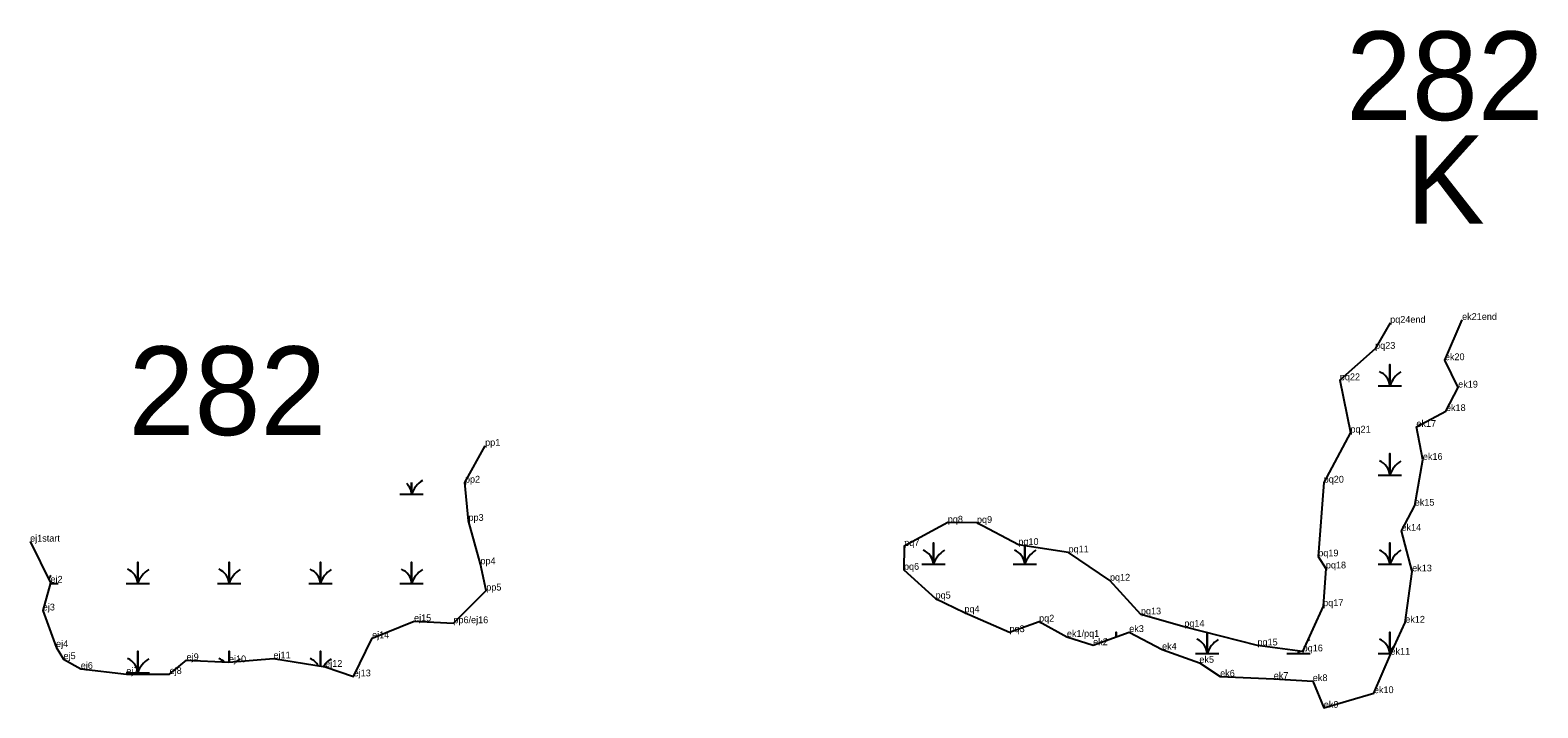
# Model space of a CAD drawing. Extents: x 2072529 to 2268796, y 436423 to 470406.
# Drawn here: x 2242590 to 2243701, y 441089 to 441588 of the extents above; entities that cross this region are included whole.
import ezdxf

# ---------------------------------------------------------------- set-up
doc = ezdxf.new("R2010")
doc.units = 0
for name, color, linetype in [('Default', 7, 'Continuous'), ('Exist Environmental Wetland Boundary', 7, 'Continuous'), ('Exist Environmental Wetland Boundary Cogo Comment', 7, 'Continuous'), ('Exist Hydro Swamp or Marsh', 7, 'Continuous'), ('Old_Level_20', 7, 'Continuous')]:
    doc.layers.add(name, color=color, linetype=linetype)

msp = doc.modelspace()

# ---------------------------------------------------------------- linework, layer by layer
at = {"layer": 'Exist Environmental Wetland Boundary'}
for points in [[(2243592.5, 441372.6), (2243581.4, 441353.4), (2243555.4, 441330.2), (2243563.2, 441291.6), (2243543.5, 441254.7), (2243539.5, 441200.3), (2243545.1, 441191.4), (2243543.1, 441163.6), (2243528, 441130.2), (2243494.7, 441134.6), (2243440.8, 441148.4), (2243408.8, 441157.5), (2243386, 441182.4), (2243355.5, 441203.2), (2243318.5, 441208.7), (2243288, 441225), (2243266.5, 441225.2), (2243234.4, 441207.9), (2243234.2, 441190.4), (2243257.5, 441169.2), (2243278.8, 441159), (2243312, 441144.4), (2243333.8, 441152.2), (2243354.3, 441140.9)], [(2243354.3, 441140.9), (2243373.6, 441134.8), (2243400.2, 441144.5), (2243424.4, 441131.5), (2243451.9, 441121.8), (2243467.2, 441111.6), (2243506.7, 441109.9), (2243535.5, 441108.3), (2243543.6, 441088.6), (2243580.5, 441099.4), (2243592.7, 441127.8), (2243603.6, 441151.4), (2243608.7, 441189.2), (2243600.8, 441219.2), (2243610.6, 441237.7), (2243616.6, 441271.5), (2243611.8, 441295.8), (2243633.6, 441307.5), (2243642.6, 441324.8), (2243632.8, 441345), (2243645.5, 441374.7)], [(2242590.3, 441211.2), (2242605.3, 441180.9), (2242599.6, 441160.4), (2242609.4, 441133.4), (2242614.9, 441124.5), (2242627.6, 441117.4), (2242661.2, 441113.4), (2242693.1, 441113.5), (2242705.6, 441123.7), (2242736.8, 441122.2), (2242769.6, 441125), (2242807.7, 441118.8), (2242828.7, 441111.8), (2242842.3, 441139.9), (2242873.2, 441152.5), (2242902.2, 441151), (2242926.4, 441175.1), (2242922.1, 441194.5), (2242913.3, 441226.5), (2242910.7, 441254.7), (2242925.6, 441281.9)]]:
    msp.add_lwpolyline(points, dxfattribs=at)
at = {"layer": 'Exist Hydro Swamp or Marsh'}
for points in [[(2243583.6, 441326.1), (2243592.2, 441326.1), (2243592.2, 441341.9), (2243592.2, 441326.1), (2243600.8, 441326.1)], [(2243583.6, 441260.3), (2243592.2, 441260.3), (2243592.2, 441276.1), (2243592.2, 441260.3), (2243600.8, 441260.3)], [(2242862.8, 441246.1), (2242871.4, 441246.1), (2242871.4, 441254.9)], [(2242871.4, 441254.9), (2242871.4, 441246.1), (2242880, 441246.1)], [(2243247.4, 441194.5), (2243256, 441194.5), (2243256, 441210.3), (2243256, 441194.5), (2243264.6, 441194.5)], [(2243583.6, 441194.5), (2243592.2, 441194.5), (2243592.2, 441210.3), (2243592.2, 441194.5), (2243600.8, 441194.5)], [(2243314.6, 441194.5), (2243323.2, 441194.5), (2243323.2, 441208)], [(2243323.2, 441208), (2243323.2, 441194.5), (2243331.8, 441194.5)], [(2242661.1, 441180.3), (2242669.7, 441180.3), (2242669.7, 441196.1), (2242669.7, 441180.3), (2242678.3, 441180.3)], [(2242728.3, 441180.3), (2242736.9, 441180.3), (2242736.9, 441196.1), (2242736.9, 441180.3), (2242745.5, 441180.3)], [(2242795.6, 441180.3), (2242804.2, 441180.3), (2242804.2, 441196.1), (2242804.2, 441180.3), (2242812.8, 441180.3)], [(2242862.8, 441180.3), (2242871.4, 441180.3), (2242871.4, 441196.1), (2242871.4, 441180.3), (2242880, 441180.3)], [(2242605.1, 441180.3), (2242611, 441180.3)], [(2243390.5, 441140.9), (2243390.5, 441144.5), (2243390.5, 441140.9)], [(2243449.1, 441128.7), (2243457.7, 441128.7), (2243457.7, 441144.1)], [(2243457.7, 441144.1), (2243457.7, 441128.7), (2243466.3, 441128.7)], [(2243583.6, 441128.7), (2243592.2, 441128.7), (2243592.2, 441144.5), (2243592.2, 441128.7), (2243593.1, 441128.7)], [(2242661.1, 441114.5), (2242669.7, 441114.5), (2242669.7, 441130.3), (2242669.7, 441114.5), (2242678.3, 441114.5)], [(2242736.9, 441122.2), (2242736.9, 441130.3), (2242736.9, 441122.2)], [(2242804.2, 441119.3), (2242804.2, 441130.3), (2242804.2, 441119.3)], [(2243516.4, 441128.7), (2243525, 441128.7), (2243525, 441130.6)], [(2243525, 441130.6), (2243525, 441128.7), (2243533.6, 441128.7)]]:
    msp.add_lwpolyline(points, dxfattribs=at)
for centre, radius, start, end in [((2243579.9, 441325.2), 12.3, 4.1403, 67.535), ((2243610.5, 441320.1), 19.2, 122.1274, 161.6222), ((2243579.9, 441259.4), 12.3, 4.1403, 67.535), ((2243610.5, 441254.3), 19.2, 122.1274, 161.6222), ((2242859.2, 441245.2), 12.3, 4.1403, 45.821), ((2242889.7, 441240.1), 19.2, 122.1274, 161.6222), ((2243243.7, 441193.6), 12.3, 4.1403, 67.535), ((2243274.2, 441188.5), 19.2, 122.1274, 161.6222), ((2243310.9, 441193.6), 12.3, 4.1403, 67.535), ((2243341.5, 441188.5), 19.2, 122.1274, 161.6222), ((2243579.9, 441193.6), 12.3, 4.1403, 67.535), ((2243610.5, 441188.5), 19.2, 122.1274, 161.6222), ((2242657.4, 441179.4), 12.3, 4.1403, 67.535), ((2242687.9, 441174.3), 19.2, 122.1274, 161.6222), ((2242724.7, 441179.4), 12.3, 4.1403, 67.535), ((2242755.2, 441174.3), 19.2, 122.1274, 161.6222), ((2242791.9, 441179.4), 12.3, 4.1403, 67.535), ((2242822.4, 441174.3), 19.2, 122.1274, 161.6222), ((2242859.2, 441179.4), 12.3, 4.1403, 67.535), ((2242889.7, 441174.3), 19.2, 122.1274, 161.6222), ((2242620.7, 441174.3), 19.2, 141.9189, 150.5403), ((2243378.2, 441127.8), 12.3, 61.372, 67.535), ((2243445.4, 441127.8), 12.3, 4.1403, 67.535), ((2243476, 441122.7), 19.2, 122.1274, 161.6222), ((2243543.2, 441122.7), 19.2, 122.1274, 127.4904), ((2243579.9, 441127.8), 12.3, 4.1403, 67.535), ((2243610.5, 441122.7), 19.2, 137.2939, 161.6222), ((2242657.4, 441113.6), 12.3, 4.1403, 67.535), ((2242687.9, 441108.5), 19.2, 122.1274, 161.6222), ((2242724.7, 441113.6), 12.3, 45.1851, 67.535), ((2242755.2, 441108.5), 19.2, 122.1274, 132.4429), ((2242791.9, 441113.6), 12.3, 28.9757, 67.535), ((2242822.4, 441108.5), 19.2, 122.1274, 146.7681), ((2243512.7, 441127.8), 12.3, 4.1403, 13.3551), ((2243543.2, 441122.7), 19.2, 155.8011, 161.6222)]:
    msp.add_arc(centre, radius, start, end, dxfattribs=at)
at = {"layer": 'Old_Level_20'}
for p, q in [((2243592.5, 441372.6), (2243592.5, 441372.6)), ((2243645.5, 441374.7), (2243645.5, 441374.7)), ((2243581.4, 441353.4), (2243581.4, 441353.4)), ((2243632.8, 441345), (2243632.8, 441345)), ((2243555.4, 441330.2), (2243555.4, 441330.2)), ((2243642.6, 441324.8), (2243642.6, 441324.8)), ((2243633.6, 441307.5), (2243633.6, 441307.5)), ((2243563.2, 441291.6), (2243563.2, 441291.6)), ((2243611.8, 441295.8), (2243611.8, 441295.8)), ((2242925.6, 441281.9), (2242925.6, 441281.9)), ((2243616.6, 441271.5), (2243616.6, 441271.5)), ((2242910.7, 441254.7), (2242910.7, 441254.7)), ((2243543.5, 441254.7), (2243543.5, 441254.7)), ((2243610.6, 441237.7), (2243610.6, 441237.7)), ((2242913.3, 441226.5), (2242913.3, 441226.5)), ((2243266.5, 441225.2), (2243266.5, 441225.2)), ((2243288, 441225), (2243288, 441225)), ((2242590.3, 441211.2), (2242590.3, 441211.2)), ((2243318.5, 441208.7), (2243318.5, 441208.7)), ((2243600.8, 441219.2), (2243600.8, 441219.2)), ((2243234.4, 441207.9), (2243234.4, 441207.9)), ((2243355.5, 441203.2), (2243355.5, 441203.2)), ((2243539.5, 441200.3), (2243539.5, 441200.3)), ((2242922.1, 441194.5), (2242922.1, 441194.5)), ((2243234.2, 441190.4), (2243234.2, 441190.4)), ((2243545.1, 441191.4), (2243545.1, 441191.4)), ((2243608.7, 441189.2), (2243608.7, 441189.2)), ((2242605.3, 441180.9), (2242605.3, 441180.9)), ((2243386, 441182.4), (2243386, 441182.4)), ((2242926.4, 441175.1), (2242926.4, 441175.1)), ((2243257.5, 441169.2), (2243257.5, 441169.2)), ((2242599.6, 441160.4), (2242599.6, 441160.4)), ((2243278.8, 441159), (2243278.8, 441159)), ((2243408.8, 441157.5), (2243408.8, 441157.5)), ((2243543.1, 441163.6), (2243543.1, 441163.6)), ((2242873.2, 441152.5), (2242873.2, 441152.5)), ((2242902.2, 441151), (2242902.2, 441151)), ((2243312, 441144.4), (2243312, 441144.4)), ((2243333.8, 441152.2), (2243333.8, 441152.2)), ((2243400.2, 441144.5), (2243400.2, 441144.5)), ((2243440.8, 441148.4), (2243440.8, 441148.4)), ((2243603.6, 441151.4), (2243603.6, 441151.4)), ((2242609.4, 441133.4), (2242609.4, 441133.4)), ((2242842.3, 441139.9), (2242842.3, 441139.9)), ((2243354.3, 441140.9), (2243354.3, 441140.9)), ((2243373.6, 441134.8), (2243373.6, 441134.8)), ((2243424.4, 441131.5), (2243424.4, 441131.5)), ((2243494.7, 441134.6), (2243494.7, 441134.6)), ((2242614.9, 441124.5), (2242614.9, 441124.5)), ((2242705.6, 441123.7), (2242705.6, 441123.7)), ((2242736.8, 441122.2), (2242736.8, 441122.2)), ((2242769.6, 441125), (2242769.6, 441125)), ((2243451.9, 441121.8), (2243451.9, 441121.8)), ((2243528, 441130.2), (2243528, 441130.2)), ((2243592.7, 441127.8), (2243592.7, 441127.8)), ((2242627.6, 441117.4), (2242627.6, 441117.4)), ((2242661.2, 441113.4), (2242661.2, 441113.4)), ((2242693.1, 441113.5), (2242693.1, 441113.5)), ((2242807.7, 441118.8), (2242807.7, 441118.8)), ((2242828.7, 441111.8), (2242828.7, 441111.8)), ((2243467.2, 441111.6), (2243467.2, 441111.6)), ((2243506.7, 441109.9), (2243506.7, 441109.9)), ((2243535.5, 441108.3), (2243535.5, 441108.3)), ((2243580.5, 441099.4), (2243580.5, 441099.4)), ((2243543.6, 441088.6), (2243543.6, 441088.6))]:
    msp.add_line(p, q, dxfattribs=at)

# ---------------------------------------------------------------- texts
at = {"layer": 'Default'}
for s, height, p in [('282', 65.34, (2243559.9, 441522.1)), ('282', 65.34, (2243559.9, 441522.1)), ('K', 65.3, (2243604, 441445.6)), ('K', 65.3, (2243604, 441445.6)), ('282', 65.34, (2242662.8, 441289.8))]:
    msp.add_text(s, height=height, dxfattribs=at).set_placement(p)
at = {"layer": 'Exist Environmental Wetland Boundary Cogo Comment'}
for s, p in [('pq24end', (2243592.5, 441372.6)), ('ek21end', (2243645.5, 441374.7)), ('pq23', (2243581.4, 441353.4)), ('ek20', (2243632.8, 441345)), ('pq22', (2243555.4, 441330.2)), ('ek19', (2243642.6, 441324.8)), ('ek18', (2243633.6, 441307.5)), ('ek17', (2243611.8, 441295.8)), ('pp1', (2242925.6, 441281.9)), ('pq21', (2243563.2, 441291.6)), ('ek16', (2243616.6, 441271.5)), ('pp2', (2242910.7, 441254.7)), ('pq20', (2243543.5, 441254.7)), ('ek15', (2243610.6, 441237.7)), ('pp3', (2242913.3, 441226.5)), ('pq8', (2243266.5, 441225.2)), ('pq9', (2243288, 441225)), ('ek14', (2243600.8, 441219.2)), ('ej1start', (2242590.3, 441211.2)), ('pq7', (2243234.4, 441207.9)), ('pq10', (2243318.5, 441208.7)), ('pp4', (2242922.1, 441194.5)), ('pq11', (2243355.5, 441203.2)), ('pq19', (2243539.5, 441200.3)), ('pq6', (2243234.2, 441190.4)), ('pq12', (2243386, 441182.4)), ('pq18', (2243545.1, 441191.4)), ('ek13', (2243608.7, 441189.2)), ('ej2', (2242605.3, 441180.9)), ('pp5', (2242926.4, 441175.1)), ('ej3', (2242599.6, 441160.4)), ('pq5', (2243257.5, 441169.2)), ('pq17', (2243543.1, 441163.6)), ('ej15', (2242873.2, 441152.5)), ('pp6/ej16', (2242902.2, 441151)), ('pq4', (2243278.8, 441159)), ('pq2', (2243333.8, 441152.2)), ('pq13', (2243408.8, 441157.5)), ('pq14', (2243440.8, 441148.4)), ('ek12', (2243603.6, 441151.4)), ('ej14', (2242842.3, 441139.9)), ('pq3', (2243312, 441144.4)), ('ek1/pq1', (2243354.3, 441140.9)), ('ek3', (2243400.2, 441144.5)), ('ej4', (2242609.4, 441133.4)), ('ek2', (2243373.6, 441134.8)), ('ek4', (2243424.4, 441131.5)), ('pq15', (2243494.7, 441134.6)), ('pq16', (2243528, 441130.2)), ('ek11', (2243592.7, 441127.8)), ('ej5', (2242614.9, 441124.5)), ('ej6', (2242627.6, 441117.4)), ('ej9', (2242705.6, 441123.7)), ('ej10', (2242736.8, 441122.2)), ('ej11', (2242769.6, 441125)), ('ej12', (2242807.7, 441118.8)), ('ek5', (2243451.9, 441121.8)), ('ej7', (2242661.2, 441113.4)), ('ej8', (2242693.1, 441113.5)), ('ej13', (2242828.7, 441111.8)), ('ek6', (2243467.2, 441111.6)), ('ek7', (2243506.7, 441109.9)), ('ek8', (2243535.5, 441108.3)), ('ek10', (2243580.5, 441099.4)), ('ek9', (2243543.6, 441088.6))]:
    msp.add_text(s, height=5, dxfattribs=at).set_placement(p)

doc.saveas('drawing.dxf')
